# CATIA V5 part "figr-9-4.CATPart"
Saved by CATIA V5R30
Part number: Part1
Bounding box of the stored display mesh (mm): x -71.324 to 69.61, y -139.735 to 0, z 0 to 45
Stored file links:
  D:\PROJECTS\CATIA V56R 2020\Resources\Parts File\c09_catia_v5_6r2020_prt\figr-9-4.CATPart
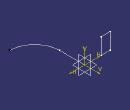
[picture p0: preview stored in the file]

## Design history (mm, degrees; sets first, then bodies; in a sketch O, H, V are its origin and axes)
Body1 (main body)
  Sketch1 on xy-plane, origin (0, 0, 0), H (1, 0, 0), V (0, 1, 0)
    line L1 (0, 0) -> (0, -70.1255)
    arc A1 centre (69.6095, -70.1255) radius 69.6095 from (0, -70.1255) to (69.6095, -139.7351) ccw
    vertical: L1 V
    tangency: A1 L1
  Sketch2 on zx-plane, origin (0, 0, 0), H (-1, 0, 0), V (0, 0, 1)
    point P1 (46.3244, 0)
    line L1 (46.3244, 0) -> (71.3244, 0)
    line L2 (71.3244, 0) -> (71.3244, 45)
    line L3 (71.3244, 45) -> (46.3244, 45)
    line L4 (46.3244, 45) -> (46.3244, 0)
    length L3 = 25
    length L2 = 45
    coincidence: P1 H
    horizontal: L1 H, L3 H
    vertical: L2 V, L4 V
  Rib1: profile Sketch2, centre curve Sketch1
